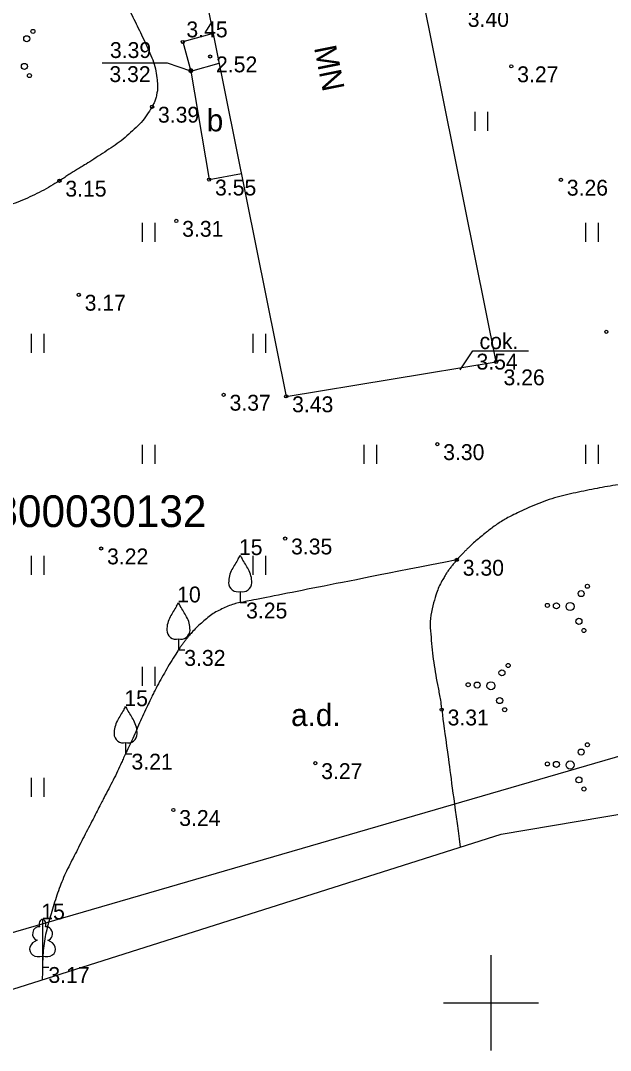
# Model space of a CAD drawing. Extents: x 321079 to 321220, y 257030 to 257220.
# Drawn here: x 321135.15 to 321153.77, y 257098.5 to 257130.98 of the extents above; entities that cross this region are included whole.
import ezdxf

# ---------------------------------------------------------------- set-up
doc = ezdxf.new("R2010")
doc.units = 0
for name, color, linetype in [('BUVE_BDET_####_####_#', 7, 'Continuous'), ('BUVE_BDET_####_TKST_#', 7, 'Continuous'), ('BUVE_EKAS_####_####_#', 7, 'Continuous'), ('BUVE_EKAS_RAKS_TKST_#', 7, 'Continuous'), ('CELI_CMAL_####_####_#', 7, 'Continuous'), ('CELI_CSEG_####_TKST_#', 7, 'Continuous'), ('GEOD_ELEM_####_####_#', 7, 'Continuous'), ('RAMI_UZMR_####_####_#', 7, 'Continuous'), ('RELJ_AATZ_####_TKST_#', 7, 'Continuous'), ('RELJ_ELEM_####_####_#', 7, 'Continuous'), ('ROBZ_KADS_####_TKST_#', 7, 'Continuous'), ('ROBZ_UZMR_####_####_#', 7, 'Continuous'), ('TERT_DIAM_####_TKST_#', 7, 'Continuous'), ('TERT_ELEM_####_####_#', 7, 'Continuous'), ('TERT_IZMT_####_TKST_#', 7, 'Continuous'), ('TERT_KONT_####_####_#', 7, 'Continuous')]:
    doc.layers.add(name, color=color, linetype=linetype)

msp = doc.modelspace()

# ---------------------------------------------------------------- linework, layer by layer
at = {"layer": 'BUVE_BDET_####_####_#'}
for points in [[(321141.236, 257130.571), (321140.276, 257130.305), (321140.53, 257129.387), (321141.424, 257129.634)], [(321149.027, 257119.969), (321149.432, 257120.569), (321151.185, 257120.569)]]:
    msp.add_lwpolyline(points, dxfattribs=at)
at = {"layer": 'BUVE_EKAS_####_####_#'}
for p, q in [((321150.164, 257120.215), (321146.269, 257139.608)), ((321139.642, 257138.491), (321143.539, 257119.128)), ((321143.539, 257119.128), (321150.164, 257120.215))]:
    msp.add_line(p, q, dxfattribs=at)
at = {"layer": 'CELI_CMAL_####_####_#'}
msp.add_lwpolyline([(321140.53, 257129.387), (321141.106, 257125.964), (321142.124, 257126.159)], dxfattribs=at)
at = {"layer": 'GEOD_ELEM_####_####_#'}
for p, q in [((321150, 257101.5), (321150, 257100)), ((321148.5, 257100), (321150, 257100)), ((321150, 257100), (321150, 257098.5)), ((321150, 257100), (321151.5, 257100))]:
    msp.add_line(p, q, dxfattribs=at)
at = {"layer": 'RAMI_UZMR_####_####_#'}
msp.add_lwpolyline([(321107.5, 257141.5), (321108.611, 257133.395), (321131.584, 257099.382), (321150.327, 257105.322), (321177.121, 257109.842), (321183.308, 257111.386), (321177.517, 257137.442), (321172.561, 257161.05), (321156.27, 257158.872), (321156.852, 257154.517), (321139.352, 257150.329), (321114.57, 257145.337)], close=True, dxfattribs=at)
at = {"layer": 'RELJ_AATZ_####_TKST_#'}
msp.add_lwpolyline([(321140.53, 257129.387), (321139.787, 257129.64), (321137.726, 257129.64)], dxfattribs=at)
at = {"layer": 'RELJ_ELEM_####_####_#'}
for centre in [(321140.276, 257130.305), (321141.137, 257129.848), (321140.528, 257129.417), (321140.53, 257129.387), (321150.644, 257129.536), (321139.305, 257128.261), (321136.381, 257125.928), (321141.106, 257125.964), (321152.209, 257125.958), (321140.069, 257124.662), (321136.991, 257122.331), (321153.641, 257121.163), (321150.164, 257120.215), (321141.564, 257119.177), (321143.539, 257119.128), (321148.307, 257117.619), (321143.506, 257114.643), (321137.698, 257114.33), (321148.925, 257113.972), (321148.447, 257109.249), (321144.457, 257107.558), (321139.976, 257106.08)]:
    msp.add_circle(centre, 0.05, dxfattribs=at)
at = {"layer": 'ROBZ_UZMR_####_####_#'}
msp.add_line((321131.975, 257101.369), (321171.804, 257112.938), dxfattribs=at)
at = {"layer": 'TERT_ELEM_####_####_#'}
for p, q in [((321149.5, 257127.5), (321149.5, 257128.1)), ((321149.9, 257127.5), (321149.9, 257128.1)), ((321139, 257124), (321139, 257124.6)), ((321139.4, 257124), (321139.4, 257124.6)), ((321153, 257124), (321153, 257124.6)), ((321153.4, 257124), (321153.4, 257124.6)), ((321135.5, 257120.5), (321135.5, 257121.1)), ((321135.9, 257120.5), (321135.9, 257121.1)), ((321142.5, 257120.5), (321142.5, 257121.1)), ((321142.9, 257120.5), (321142.9, 257121.1)), ((321139, 257117), (321139, 257117.6)), ((321139.4, 257117), (321139.4, 257117.6)), ((321146, 257117), (321146, 257117.6)), ((321146.4, 257117), (321146.4, 257117.6)), ((321153, 257117), (321153, 257117.6)), ((321153.4, 257117), (321153.4, 257117.6)), ((321135.5, 257113.5), (321135.5, 257114.1)), ((321135.9, 257113.5), (321135.9, 257114.1)), ((321142.5, 257113.5), (321142.5, 257114.1)), ((321142.9, 257113.5), (321142.9, 257114.1)), ((321142.087, 257112.975), (321142.087, 257112.623)), ((321142.087, 257112.623), (321142.287, 257112.623)), ((321140.136, 257111.481), (321140.136, 257111.129)), ((321140.136, 257111.129), (321140.336, 257111.129)), ((321139, 257110), (321139, 257110.6)), ((321139.4, 257110), (321139.4, 257110.6)), ((321138.469, 257108.209), (321138.469, 257107.857)), ((321138.469, 257107.857), (321138.669, 257107.857)), ((321135.5, 257106.5), (321135.5, 257107.1)), ((321135.9, 257106.5), (321135.9, 257107.1)), ((321135.847, 257101.476), (321135.847, 257101.129)), ((321135.847, 257101.129), (321136.047, 257101.129))]:
    msp.add_line(p, q, dxfattribs=at)
for points in [[(321135.847, 257102.629), (321135.847, 257101.476)], [(321135.937, 257102.397), (321135.936, 257102.398)]]:
    msp.add_lwpolyline(points, dxfattribs=at)
for centre, radius in [((321135.348, 257130.408), 0.096), ((321135.544, 257130.639), 0.064), ((321135.276, 257129.533), 0.096), ((321135.434, 257129.244), 0.064), ((321153.044, 257113.139), 0.064), ((321152.848, 257112.908), 0.096), ((321151.782, 257112.534), 0.064), ((321152.066, 257112.521), 0.096), ((321152.5, 257112.5), 0.128), ((321152.776, 257112.033), 0.096), ((321152.934, 257111.744), 0.064), ((321150.544, 257110.639), 0.064), ((321150.348, 257110.408), 0.096), ((321149.282, 257110.034), 0.064), ((321149.566, 257110.021), 0.096), ((321150, 257110), 0.128), ((321150.276, 257109.533), 0.096), ((321150.434, 257109.244), 0.064), ((321152.848, 257107.908), 0.096), ((321153.044, 257108.139), 0.064), ((321151.782, 257107.534), 0.064), ((321152.066, 257107.521), 0.096), ((321152.5, 257107.5), 0.128), ((321152.776, 257107.033), 0.096), ((321152.934, 257106.744), 0.064)]:
    msp.add_circle(centre, radius, dxfattribs=at)
for centre, radius, start, end in [((321154.712, 257106.227), 14.88, 148.4844, 149.9901), ((321141.67, 257114.261), 0.439, 324.3837, 341.712), ((321142.504, 257114.261), 0.439, 198.288, 215.6163), ((321129.462, 257106.227), 14.88, 30.0099, 31.5156), ((321142.611, 257113.248), 0.89, 151.757, 179.9138), ((321141.563, 257113.248), 0.89, 0.0862, 28.243), ((321142.011, 257113.254), 0.29, 181.0782, 285.2823), ((321142.163, 257113.254), 0.29, 254.7177, 358.9218), ((321139.719, 257112.767), 0.439, 324.3837, 341.712), ((321140.553, 257112.767), 0.439, 198.288, 215.6163), ((321152.761, 257104.733), 14.88, 148.4844, 149.9901), ((321127.511, 257104.733), 14.88, 30.0099, 31.5156), ((321140.66, 257111.754), 0.89, 151.757, 179.9138), ((321139.612, 257111.754), 0.89, 0.0862, 28.243), ((321140.06, 257111.76), 0.29, 181.0782, 285.2823), ((321140.212, 257111.76), 0.29, 254.7177, 358.9218), ((321138.052, 257109.495), 0.439, 324.3837, 341.712), ((321138.886, 257109.495), 0.439, 198.288, 215.6163), ((321151.094, 257101.461), 14.88, 148.4844, 149.9901), ((321125.844, 257101.461), 14.88, 30.0099, 31.5156), ((321138.993, 257108.482), 0.89, 151.757, 179.9138), ((321137.945, 257108.482), 0.89, 0.0862, 28.243), ((321138.393, 257108.488), 0.29, 181.0782, 285.2823), ((321138.545, 257108.488), 0.29, 254.7177, 358.9218)]:
    msp.add_arc(centre, radius, start, end, dxfattribs=at)
for centre, major_axis, ratio, start_param, end_param in [((321135.847, 257102.479), (0, -0.15), 0.707107, 3.14537, 5.287485), ((321135.847, 257102.479), (0, -0.15), 0.707107, 0.995701, 3.137816), ((321135.719, 257102.184), (-0.039, -0.212), 0.861323, 3.141593, 6.283185), ((321135.975, 257102.184), (0.039, -0.212), 0.861323, 0, 3.141593), ((321135.757, 257101.722), (0.307, 0.095), 0.814445, 1.570796, 4.752015), ((321135.937, 257101.722), (-0.307, 0.095), 0.814445, 1.531171, 4.712389)]:
    msp.add_ellipse(centre, major_axis=major_axis, ratio=ratio, start_param=start_param, end_param=end_param, dxfattribs=at)
at = {"layer": 'TERT_KONT_####_####_#'}
for points in [[(321129.296, 257148.304), (321129.341, 257148.261), (321129.386, 257148.219), (321129.431, 257148.175), (321129.997, 257147.629), (321130.535, 257147.084), (321131.007, 257146.464), (321131.229, 257146.173), (321131.445, 257145.88), (321131.641, 257145.571), (321131.732, 257145.427), (321131.822, 257145.282), (321131.907, 257145.134), (321131.947, 257145.064), (321131.986, 257144.992), (321132.026, 257144.921), (321132.063, 257144.852), (321132.099, 257144.783), (321132.134, 257144.712), (321132.197, 257144.587), (321132.235, 257144.453), (321132.271, 257144.317), (321132.304, 257144.188), (321132.307, 257144.052), (321132.294, 257143.922), (321132.267, 257143.648), (321132.204, 257143.378), (321132.049, 257143.129), (321131.664, 257142.512), (321131.238, 257142.013), (321130.74, 257141.535), (321130.167, 257140.985), (321129.559, 257140.48), (321128.996, 257139.924), (321128.727, 257139.659), (321128.461, 257139.391), (321128.207, 257139.11), (321128.089, 257138.98), (321127.978, 257138.844), (321127.876, 257138.701), (321127.78, 257138.567), (321127.689, 257138.431), (321127.604, 257138.29), (321127.372, 257137.904), (321127.146, 257137.516), (321126.921, 257137.126), (321126.204, 257135.885), (321125.508, 257134.637), (321124.83, 257133.371), (321124.395, 257132.558), (321124.066, 257131.698), (321123.781, 257130.816), (321123.649, 257130.407), (321123.546, 257129.995), (321123.474, 257129.573), (321123.44, 257129.372), (321123.41, 257129.171), (321123.392, 257128.968), (321123.382, 257128.868), (321123.376, 257128.769), (321123.37, 257128.67), (321123.364, 257128.572), (321123.362, 257128.474), (321123.363, 257128.376), (321123.363, 257128.279), (321123.397, 257128.188), (321123.453, 257128.099), (321123.517, 257127.997), (321123.596, 257127.929), (321123.697, 257127.871), (321123.95, 257127.726), (321124.201, 257127.63), (321124.477, 257127.566), (321124.773, 257127.498), (321125.07, 257127.468), (321125.365, 257127.469), (321125.586, 257127.469), (321125.807, 257127.489), (321126.024, 257127.585), (321126.11, 257127.623), (321126.176, 257127.675), (321126.244, 257127.735), (321126.317, 257127.8), (321126.385, 257127.864), (321126.446, 257127.94), (321126.585, 257128.113), (321126.721, 257128.288), (321126.81, 257128.488), (321127.025, 257128.97), (321127.24, 257129.453), (321127.454, 257129.935), (321127.682, 257130.449), (321127.909, 257130.964), (321128.138, 257131.479), (321128.244, 257131.718), (321128.394, 257131.934), (321128.552, 257132.146), (321128.662, 257132.293), (321128.779, 257132.43), (321128.913, 257132.555), (321128.956, 257132.595), (321128.999, 257132.633), (321129.045, 257132.669), (321129.307, 257132.877), (321129.57, 257133.08), (321129.838, 257133.28), (321130.141, 257133.505), (321130.45, 257133.717), (321130.763, 257133.93), (321131.417, 257134.374), (321132.085, 257134.734), (321132.823, 257135.088), (321133.478, 257135.403), (321134.165, 257135.57), (321134.85, 257135.629), (321135.141, 257135.654), (321135.444, 257135.606), (321135.734, 257135.506), (321135.875, 257135.457), (321136.001, 257135.399), (321136.124, 257135.317), (321136.251, 257135.233), (321136.366, 257135.144), (321136.47, 257135.034), (321136.693, 257134.798), (321136.896, 257134.556), (321137.073, 257134.288), (321137.256, 257134.01), (321137.432, 257133.732), (321137.583, 257133.438), (321137.739, 257133.135), (321137.891, 257132.832), (321138.033, 257132.524), (321138.177, 257132.212), (321138.309, 257131.894), (321138.456, 257131.583), (321138.59, 257131.301), (321138.733, 257131.023), (321138.869, 257130.742), (321139.009, 257130.456), (321139.139, 257130.17), (321139.267, 257129.874), (321139.384, 257129.605), (321139.444, 257129.316), (321139.472, 257129.03), (321139.485, 257128.899), (321139.474, 257128.764), (321139.446, 257128.633), (321139.433, 257128.568), (321139.415, 257128.506), (321139.391, 257128.443), (321139.367, 257128.38), (321139.34, 257128.32), (321139.305, 257128.261), (321139.147, 257127.999), (321138.966, 257127.764), (321138.743, 257127.556), (321138.511, 257127.34), (321138.274, 257127.139), (321138.012, 257126.967), (321137.742, 257126.789), (321137.472, 257126.612), (321137.197, 257126.441), (321137.059, 257126.356), (321136.921, 257126.272), (321136.784, 257126.186), (321136.648, 257126.102), (321136.516, 257126.013), (321136.381, 257125.928), (321136.104, 257125.753), (321135.818, 257125.594), (321135.521, 257125.454), (321135.219, 257125.311), (321134.907, 257125.196), (321134.594, 257125.083), (321133.961, 257124.856), (321133.312, 257124.683), (321132.677, 257124.46), (321132.063, 257124.245), (321131.471, 257123.99), (321130.897, 257123.67), (321130.617, 257123.514), (321130.371, 257123.316), (321130.143, 257123.092), (321130.026, 257122.978), (321129.916, 257122.862), (321129.814, 257122.736), (321129.763, 257122.671), (321129.713, 257122.606), (321129.664, 257122.538), (321129.615, 257122.47), (321129.568, 257122.4), (321129.524, 257122.327), (321129.259, 257121.895), (321129.047, 257121.444), (321128.858, 257120.971), (321128.674, 257120.511), (321128.527, 257120.045), (321128.449, 257119.559), (321128.293, 257118.586), (321128.187, 257117.612), (321128.124, 257116.631), (321128.06, 257115.644), (321128.061, 257114.653), (321127.991, 257113.666), (321127.956, 257113.177), (321127.906, 257112.691), (321127.823, 257112.207), (321127.74, 257111.725), (321127.638, 257111.249), (321127.494, 257110.784), (321127.116, 257109.561), (321126.739, 257108.338), (321126.361, 257107.115)], [(321165.978, 257128.056), (321165.719, 257128.031), (321165.461, 257128.006), (321165.202, 257127.981), (321165.12, 257127.973), (321165.042, 257127.949), (321164.965, 257127.917), (321164.886, 257127.883), (321164.815, 257127.84), (321164.748, 257127.787), (321164.679, 257127.733), (321164.613, 257127.677), (321164.55, 257127.617), (321164.487, 257127.556), (321164.426, 257127.495), (321164.367, 257127.43), (321164.32, 257127.379), (321164.278, 257127.325), (321164.237, 257127.269), (321164.197, 257127.215), (321164.167, 257127.158), (321164.137, 257127.097), (321164.079, 257126.975), (321164.04, 257126.849), (321164.019, 257126.719), (321163.973, 257126.437), (321163.962, 257126.131), (321164.053, 257125.859), (321164.27, 257125.211), (321164.509, 257124.572), (321164.731, 257123.926), (321164.939, 257123.319), (321165.144, 257122.71), (321165.338, 257122.1), (321165.411, 257121.87), (321165.364, 257121.611), (321165.282, 257121.374), (321165.243, 257121.264), (321165.189, 257121.168), (321165.106, 257121.084), (321165.013, 257120.991), (321164.92, 257120.912), (321164.809, 257120.851), (321164.154, 257120.491), (321163.501, 257120.137), (321162.83, 257119.815), (321162.161, 257119.493), (321161.495, 257119.165), (321160.819, 257118.86), (321160.143, 257118.555), (321159.465, 257118.255), (321158.786, 257117.955), (321158.107, 257117.655), (321157.426, 257117.361), (321156.743, 257117.07), (321156.425, 257116.935), (321156.099, 257116.819), (321155.766, 257116.727), (321155.437, 257116.635), (321155.104, 257116.564), (321154.771, 257116.492), (321154.105, 257116.348), (321153.431, 257116.25), (321152.764, 257116.107), (321152.083, 257115.96), (321151.428, 257115.734), (321150.792, 257115.429), (321150.449, 257115.264), (321150.137, 257115.062), (321149.841, 257114.828), (321149.681, 257114.702), (321149.525, 257114.575), (321149.378, 257114.436), (321149.301, 257114.363), (321149.224, 257114.289), (321149.15, 257114.213), (321149.112, 257114.174), (321149.074, 257114.135), (321149.037, 257114.095), (321149.018, 257114.075), (321149, 257114.054), (321148.981, 257114.034), (321148.962, 257114.014), (321148.944, 257113.993), (321148.925, 257113.972), (321148.844, 257113.881), (321148.769, 257113.785), (321148.695, 257113.687), (321148.626, 257113.596), (321148.567, 257113.499), (321148.509, 257113.4), (321148.4, 257113.214), (321148.316, 257113.027), (321148.252, 257112.817), (321148.132, 257112.422), (321148.07, 257112.027), (321148.101, 257111.632), (321148.133, 257111.233), (321148.178, 257110.834), (321148.243, 257110.436), (321148.308, 257110.038), (321148.394, 257109.647), (321148.447, 257109.249), (321148.641, 257107.803), (321148.836, 257106.357), (321149.03, 257104.911)], [(321148.925, 257113.972), (321146.646, 257113.522), (321144.366, 257113.073), (321142.087, 257112.623), (321141.887, 257112.583), (321141.696, 257112.51), (321141.508, 257112.422), (321141.317, 257112.333), (321141.145, 257112.218), (321140.984, 257112.082), (321140.819, 257111.943), (321140.664, 257111.8), (321140.523, 257111.639), (321140.452, 257111.558), (321140.384, 257111.476), (321140.32, 257111.39), (321140.256, 257111.305), (321140.194, 257111.219), (321140.136, 257111.129), (321139.967, 257110.867), (321139.805, 257110.602), (321139.654, 257110.33), (321139.506, 257110.063), (321139.36, 257109.796), (321139.231, 257109.52), (321138.972, 257108.968), (321138.727, 257108.409), (321138.469, 257107.857), (321138.339, 257107.58), (321138.215, 257107.301), (321138.076, 257107.028), (321137.936, 257106.753), (321137.793, 257106.48), (321137.652, 257106.206), (321137.37, 257105.658), (321137.089, 257105.11), (321136.809, 257104.562), (321136.535, 257104.025), (321136.317, 257103.468), (321136.141, 257102.883), (321135.967, 257102.307), (321135.86, 257101.722), (321135.847, 257101.129), (321135.844, 257100.996), (321135.841, 257100.863), (321135.838, 257100.73)]]:
    msp.add_open_spline(points, degree=3, dxfattribs=at)

# ---------------------------------------------------------------- texts
at = {"layer": 'BUVE_BDET_####_TKST_#'}
for s, p in [('cok.', (321149.641, 257120.62)), (' 3.54', (321149.359, 257119.974))]:
    msp.add_text(s, height=0.5, dxfattribs=at).set_placement(p)
at = {"layer": 'BUVE_EKAS_RAKS_TKST_#'}
msp.add_text('MN', height=0.7, rotation=281.3793, dxfattribs=at).set_placement((321144.414, 257130.128))
at = {"layer": 'CELI_CSEG_####_TKST_#'}
msp.add_text('b', height=0.7, dxfattribs=at).set_placement((321141.032, 257127.485))
at = {"layer": 'RELJ_AATZ_####_TKST_#'}
for s, p in [(' 3.40', (321149.083, 257130.78)), (' 3.45', (321140.202, 257130.451)), (' 3.39', (321137.789, 257129.8)), (' 2.52', (321141.137, 257129.348)), (' 3.32', (321137.772, 257129.041)), (' 3.27', (321150.644, 257129.036)), (' 3.39', (321139.305, 257127.761)), (' 3.15', (321136.381, 257125.428)), (' 3.55', (321141.106, 257125.464)), (' 3.26', (321152.209, 257125.458)), (' 3.31', (321140.069, 257124.162)), (' 3.17', (321136.991, 257121.831)), (' 3.26', (321150.211, 257119.477)), (' 3.37', (321141.564, 257118.677)), (' 3.43', (321143.539, 257118.628)), (' 3.30', (321148.307, 257117.119)), (' 3.35', (321143.506, 257114.143)), (' 3.22', (321137.698, 257113.83)), (' 3.30', (321148.925, 257113.472)), (' 3.25', (321142.087, 257112.123)), (' 3.32', (321140.136, 257110.629)), (' 3.31', (321148.447, 257108.749)), (' 3.21', (321138.469, 257107.357)), (' 3.27', (321144.457, 257107.058)), (' 3.24', (321139.976, 257105.58)), (' 3.17', (321135.847, 257100.629))]:
    msp.add_text(s, height=0.5, dxfattribs=at).set_placement(p)
at = {"layer": 'ROBZ_KADS_####_TKST_#'}
msp.add_text('64800030132', height=1, dxfattribs=at).set_placement((321132.84, 257115.006))
at = {"layer": 'TERT_DIAM_####_TKST_#'}
for s, p in [(' 15', (321141.862, 257114.123)), (' 10', (321139.911, 257112.629)), (' 15', (321138.244, 257109.357)), (' 15', (321135.622, 257102.629))]:
    msp.add_text(s, height=0.5, dxfattribs=at).set_placement(p)
at = {"layer": 'TERT_IZMT_####_TKST_#'}
msp.add_text('a.d.', height=0.7, dxfattribs=at).set_placement((321143.693, 257108.73))

doc.saveas('drawing.dxf')
